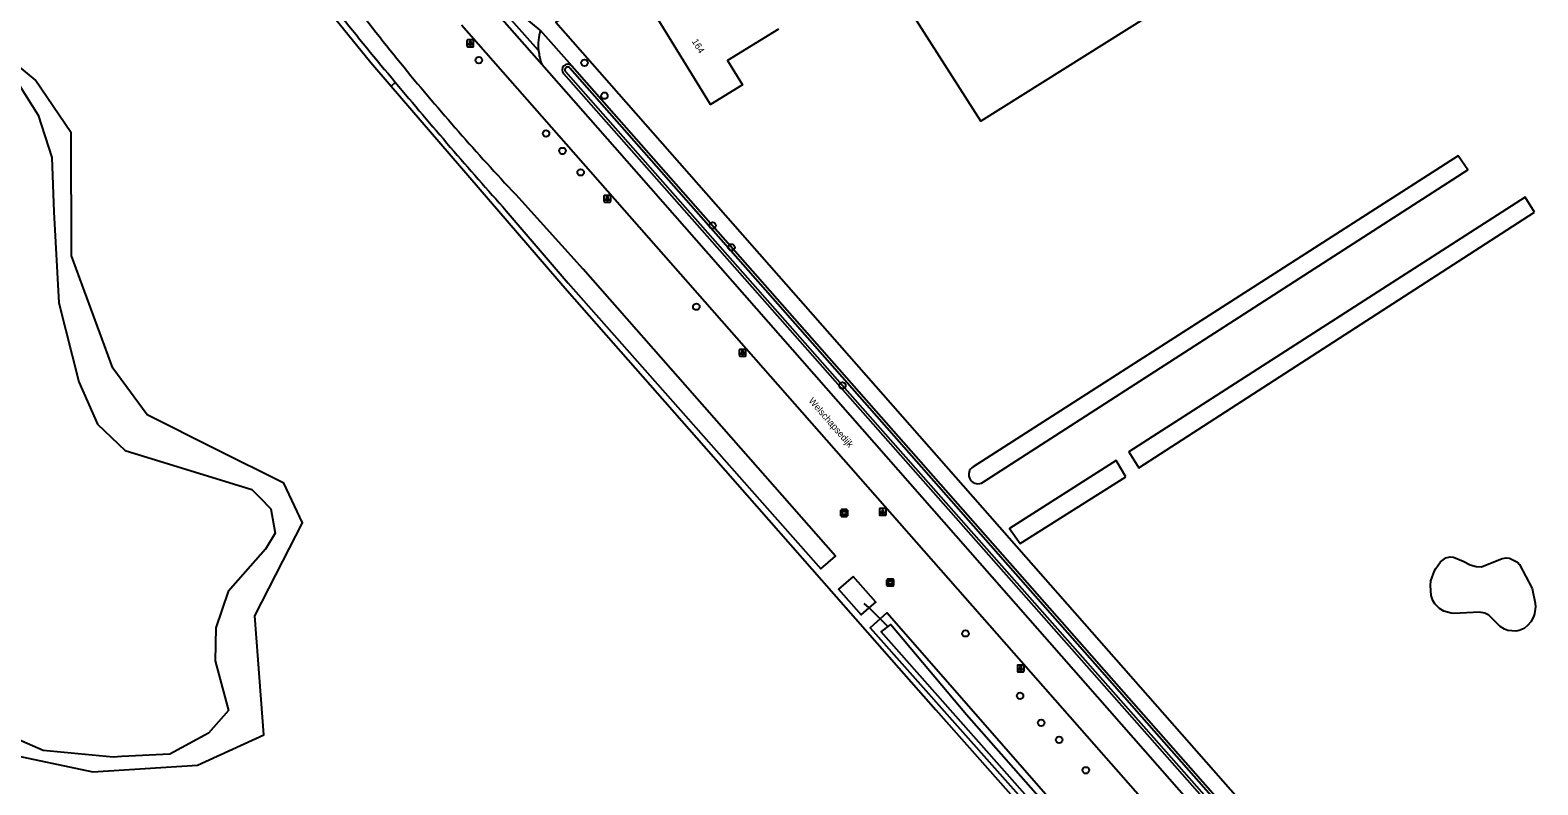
# Model space of a CAD drawing. Extents: x 156061 to 157804, y 383451 to 385640.
# Drawn here: x 157264.2 to 157488.8, y 384085.5 to 384198 of the extents above; entities that cross this region are included whole.
import ezdxf

# ---------------------------------------------------------------- set-up
doc = ezdxf.new("R2010")
doc.units = 0
for name, color, linetype in [('IMGEO_Berm_groen', 7, 'Continuous'), ('IMGEO_Boom', 7, 'Continuous'), ('IMGEO_Duiker', 7, 'Continuous'), ('IMGEO_Groenvoorziening', 7, 'Continuous'), ('IMGEO_Hek', 7, 'Continuous'), ('IMGEO_Lichtpunt', 7, 'Continuous'), ('IMGEO_Meer_plas_ven_vijver', 7, 'Continuous'), ('IMGEO_Openbare_ruimte_label', 7, 'Continuous'), ('IMGEO_Pand', 7, 'Continuous'), ('IMGEO_Pand_nummerreeks', 7, 'Continuous'), ('IMGEO_Parkeervlak_open', 7, 'Continuous'), ('IMGEO_Rijbaan_lokaal_gesloten', 7, 'Continuous'), ('IMGEO_Rijbaan_lokaal_open', 7, 'Continuous'), ('IMGEO_Verklikker', 7, 'Continuous'), ('IMGEO_Waterloop', 7, 'Continuous')]:
    doc.layers.add(name, color=color, linetype=linetype)

msp = doc.modelspace()

# ---------------------------------------------------------------- linework, layer by layer
at = {"layer": 'IMGEO_Berm_groen'}
for points in [[(157340.2, 384197.97), (157344.9, 384192.66)], [(157317.96, 384189.64), (157318.6, 384190.2)], [(157463.38, 384056.98), (157462.83, 384056.5), (157343.68, 384191.47)], [(157317.96, 384189.64), (157344.19, 384159.18), (157364.55, 384136), (157393.61, 384102.92), (157399.11, 384096.66), (157446.05, 384043.69), (157456.41, 384032.18), (157483.79, 384000), (157500, 383980.87), (157519.27, 383957.9)], [(157448.89, 384045.9), (157391.84, 384111.13), (157390.82, 384110.23), (157389.32, 384108.91), (157446.91, 384044.08), (157447.97, 384045.05)]]:
    msp.add_lwpolyline(points, dxfattribs=at)
msp.add_arc((157344.3, 384192.04), 0.853, 45.9281, 222.4567, dxfattribs=at)
at = {"layer": 'IMGEO_Boom'}
for centre in [(157331.05, 384193.51), (157346.78, 384193.11), (157349.74, 384188.2), (157341.05, 384182.56), (157343.51, 384179.96), (157346.21, 384176.77), (157365.87, 384168.86), (157368.67, 384165.6), (157363.44, 384156.75), (157385.2, 384145.03), (157403.54, 384108.07), (157411.67, 384098.76), (157414.8, 384094.75), (157417.5, 384092.21), (157421.48, 384087.66)]:
    msp.add_circle(centre, 0.489, dxfattribs=at)
at = {"layer": 'IMGEO_Duiker'}
msp.add_lwpolyline([(157391.93, 384109.15), (157390.82, 384110.23), (157389.17, 384111.85), (157388.46, 384112.54)], dxfattribs=at)
at = {"layer": 'IMGEO_Groenvoorziening'}
for points in [[(157152.75, 384380.64), (157157.1, 384375.67), (157214.42, 384310.24), (157233.65, 384288.31), (157235.49, 384286.21), (157267.06, 384250), (157294.3, 384218.6), (157310.23, 384198.96), (157314.94, 384193.15), (157317.96, 384189.64)], [(157375.38, 384222.59), (157376.59, 384220.76), (157342.51, 384199.14), (157412.58, 384119.43), (157466.22, 384058.41)], [(157260.38, 384090.24), (157273.54, 384087.41), (157289.11, 384088.41), (157299.01, 384092.93), (157298.16, 384104.12), (157297.67, 384110.68), (157301.84, 384118.84), (157304.75, 384124.52), (157301.98, 384130.44), (157291.8, 384135.54), (157281.61, 384140.64), (157276.51, 384147.57), (157270.36, 384164.31), (157270.29, 384182.67), (157264.93, 384190.55), (157259.77, 384194.82)], [(157344.9, 384192.66), (157463.98, 384057.5), (157463.38, 384056.98)], [(157477.67, 384118.84), (157478.74, 384118.28), (157479.61, 384118.03), (157480.43, 384117.98), (157483.48, 384119.23), (157484.08, 384119.32), (157484.59, 384119.3), (157485.78, 384118.66), (157486.06, 384118.35), (157487.98, 384114.75), (157488.42, 384112.58), (157488.45, 384112.03), (157488.33, 384110.99), (157488.18, 384110.55), (157487.75, 384109.78), (157487.34, 384109.28), (157486.77, 384108.81), (157486.05, 384108.5), (157485.52, 384108.4), (157484.36, 384108.49), (157483.82, 384108.7), (157483.18, 384109.1), (157481.5, 384110.76), (157480.93, 384111.09), (157480.14, 384111.22), (157476.32, 384111.02), (157475.92, 384111.06), (157474.82, 384111.39), (157474.15, 384111.79), (157473.46, 384112.48), (157473.19, 384112.96), (157472.94, 384113.69), (157472.81, 384115.22), (157472.89, 384115.91), (157473.4, 384117.41), (157473.59, 384117.76), (157474.32, 384118.74), (157475.1, 384119.31), (157475.75, 384119.5), (157476.27, 384119.45), (157477.67, 384118.84)]]:
    msp.add_lwpolyline(points, dxfattribs=at)
at = {"layer": 'IMGEO_Hek'}
msp.add_lwpolyline([(157376.59, 384220.76), (157342.51, 384199.14), (157412.58, 384119.43), (157466.22, 384058.41)], dxfattribs=at)
at = {"layer": 'IMGEO_Lichtpunt'}
for p, q in [((157329.26, 384196.41), (157329.26, 384195.6)), ((157329.26, 384196.41), (157329.26, 384195.6)), ((157330.16, 384196.5), (157329.36, 384196.5)), ((157330.16, 384196.5), (157329.36, 384196.5)), ((157329.36, 384195.5), (157330.16, 384195.5)), ((157329.36, 384195.5), (157330.16, 384195.5)), ((157330.26, 384195.6), (157330.26, 384196.41)), ((157330.26, 384195.6), (157330.26, 384196.41)), ((157349.68, 384173.24), (157349.68, 384172.43)), ((157349.68, 384173.24), (157349.68, 384172.43)), ((157350.59, 384173.33), (157349.78, 384173.33)), ((157350.59, 384173.33), (157349.78, 384173.33)), ((157349.78, 384172.34), (157350.59, 384172.34)), ((157349.78, 384172.34), (157350.59, 384172.34)), ((157350.68, 384172.43), (157350.68, 384173.24)), ((157350.68, 384172.43), (157350.68, 384173.24)), ((157369.83, 384150.3), (157369.83, 384149.49)), ((157369.83, 384150.3), (157369.83, 384149.49)), ((157370.73, 384150.39), (157369.93, 384150.39)), ((157370.73, 384150.39), (157369.93, 384150.39)), ((157370.83, 384149.49), (157370.83, 384150.3)), ((157370.83, 384149.49), (157370.83, 384150.3)), ((157369.93, 384149.4), (157370.73, 384149.4)), ((157369.93, 384149.4), (157370.73, 384149.4)), ((157390.73, 384126.57), (157390.73, 384125.76)), ((157390.73, 384126.57), (157390.73, 384125.76)), ((157391.63, 384126.66), (157390.82, 384126.66)), ((157391.63, 384126.66), (157390.82, 384126.66)), ((157390.82, 384125.66), (157391.63, 384125.66)), ((157390.82, 384125.66), (157391.63, 384125.66)), ((157391.72, 384125.76), (157391.72, 384126.57)), ((157391.72, 384125.76), (157391.72, 384126.57)), ((157411.27, 384103.25), (157411.27, 384102.45)), ((157411.27, 384103.25), (157411.27, 384102.45)), ((157412.18, 384103.35), (157411.37, 384103.35)), ((157412.18, 384103.35), (157411.37, 384103.35)), ((157412.27, 384102.45), (157412.27, 384103.25)), ((157412.27, 384102.45), (157412.27, 384103.25)), ((157411.37, 384102.35), (157412.18, 384102.35)), ((157411.37, 384102.35), (157412.18, 384102.35))]:
    msp.add_line(p, q, dxfattribs=at)
for points in [[(157329.64, 384196.07), (157329.68, 384196.04), (157329.49, 384195.78), (157329.45, 384195.81), (157329.64, 384196.07)], [(157329.74, 384196.02), (157329.79, 384196.02), (157329.79, 384195.7), (157329.74, 384195.7), (157329.74, 384196.02)], [(157329.85, 384196.04), (157329.89, 384196.07), (157330.07, 384195.81), (157330.04, 384195.78), (157329.85, 384196.04)], [(157350.06, 384172.9), (157350.1, 384172.87), (157349.91, 384172.61), (157349.87, 384172.64), (157350.06, 384172.9)], [(157350.16, 384172.85), (157350.21, 384172.85), (157350.21, 384172.53), (157350.16, 384172.53), (157350.16, 384172.85)], [(157350.27, 384172.87), (157350.31, 384172.9), (157350.49, 384172.64), (157350.46, 384172.61), (157350.27, 384172.87)], [(157370.21, 384149.96), (157370.25, 384149.93), (157370.06, 384149.67), (157370.02, 384149.7), (157370.21, 384149.96)], [(157370.31, 384149.91), (157370.36, 384149.91), (157370.36, 384149.59), (157370.31, 384149.59), (157370.31, 384149.91)], [(157370.42, 384149.93), (157370.46, 384149.96), (157370.64, 384149.7), (157370.61, 384149.67), (157370.42, 384149.93)], [(157391.1, 384126.23), (157391.14, 384126.2), (157390.95, 384125.94), (157390.91, 384125.97), (157391.1, 384126.23)], [(157391.2, 384126.18), (157391.25, 384126.18), (157391.25, 384125.86), (157391.2, 384125.86), (157391.2, 384126.18)], [(157391.31, 384126.2), (157391.35, 384126.23), (157391.54, 384125.97), (157391.5, 384125.94), (157391.31, 384126.2)], [(157411.65, 384102.92), (157411.69, 384102.89), (157411.5, 384102.63), (157411.46, 384102.66), (157411.65, 384102.92)], [(157411.75, 384102.87), (157411.8, 384102.87), (157411.8, 384102.55), (157411.75, 384102.55), (157411.75, 384102.87)], [(157411.86, 384102.89), (157411.9, 384102.92), (157412.08, 384102.65), (157412.05, 384102.63), (157411.86, 384102.89)]]:
    msp.add_lwpolyline(points, dxfattribs=at)
for centre in [(157329.76, 384196.2), (157350.18, 384173.04), (157370.33, 384150.1), (157391.23, 384126.36), (157411.77, 384103.05)]:
    msp.add_circle(centre, 0.0994, dxfattribs=at)
for centre, start, end in [((157329.36, 384196.41), 90, 180), ((157329.36, 384196.41), 90, 180), ((157329.36, 384195.6), 180, 270), ((157329.36, 384195.6), 180, 270), ((157330.16, 384196.41), 0, 90), ((157330.16, 384196.41), 0, 90), ((157330.16, 384195.6), 270, 0), ((157330.16, 384195.6), 270, 360), ((157349.78, 384173.24), 90, 180), ((157349.78, 384173.24), 90, 180), ((157349.78, 384172.43), 180, 270), ((157349.78, 384172.43), 180, 270), ((157350.59, 384173.24), 0, 90), ((157350.59, 384173.24), 0, 90), ((157350.59, 384172.43), 270, 0), ((157350.59, 384172.43), 270, 360), ((157369.93, 384150.3), 90, 180), ((157369.93, 384150.3), 90, 180), ((157370.73, 384150.3), 0, 90), ((157370.73, 384150.3), 0, 90), ((157369.93, 384149.49), 180, 270), ((157369.93, 384149.49), 180, 270), ((157370.73, 384149.49), 270, 0), ((157370.73, 384149.49), 270, 360), ((157390.82, 384126.57), 90, 180), ((157390.82, 384126.57), 90, 180), ((157390.82, 384125.76), 180, 270), ((157390.82, 384125.76), 180, 270), ((157391.63, 384126.57), 0, 90), ((157391.63, 384126.57), 0, 90), ((157391.63, 384125.76), 270, 0), ((157391.63, 384125.76), 270, 360), ((157411.37, 384103.25), 90, 180), ((157411.37, 384103.25), 90, 180), ((157411.37, 384102.45), 180, 270), ((157411.37, 384102.45), 180, 270), ((157412.18, 384103.25), 0, 90), ((157412.18, 384103.25), 0, 90), ((157412.18, 384102.45), 270, 0), ((157412.18, 384102.45), 270, 360)]:
    msp.add_arc(centre, 0.0946, start, end, dxfattribs=at)
at = {"layer": 'IMGEO_Meer_plas_ven_vijver'}
msp.add_lwpolyline([(157262.61, 384189.74), (157265.41, 384185.28), (157267.41, 384178.99), (157267.71, 384170.88), (157268.45, 384157.32), (157271.43, 384145.57), (157274.25, 384139.26), (157278.33, 384135.3), (157297.2, 384129.51), (157298.35, 384128.36), (157300.07, 384126.64), (157300.72, 384122.98), (157299.24, 384120.63), (157293.68, 384114.31), (157291.86, 384108.9), (157291.78, 384103.96), (157293.73, 384096.58), (157290.78, 384093.19), (157285.01, 384090.09), (157277.83, 384089.7), (157276.56, 384089.63), (157266.14, 384090.62), (157260.58, 384093.05)], dxfattribs=at)
at = {"layer": 'IMGEO_Pand'}
msp.add_lwpolyline([(157375.67, 384198.1), (157368.09, 384193.43), (157370.31, 384189.84), (157365.56, 384186.91), (157356.56, 384201.5)], dxfattribs=at)
at = {"layer": 'IMGEO_Parkeervlak_open'}
msp.add_lwpolyline([(157435.58, 384300.77), (157435.68, 384298.54), (157441.16, 384290.01), (157442.6, 384290.91), (157453.76, 384273.49), (157468.36, 384250), (157480.13, 384231.06), (157405.83, 384184.39), (157382.46, 384221.08)], dxfattribs=at)
at = {"layer": 'IMGEO_Rijbaan_lokaal_gesloten'}
for points in [[(157340.41, 384192.86), (157332.28, 384202.11)], [(157328.46, 384198.78), (157342.96, 384182.28), (157456.76, 384052.82)], [(157461.84, 384054.56), (157351.29, 384180.48), (157340.41, 384192.86)]]:
    msp.add_lwpolyline(points, dxfattribs=at)
at = {"layer": 'IMGEO_Rijbaan_lokaal_open'}
for points in [[(157339.93, 384194.95), (157333.81, 384201.8)], [(157340.2, 384197.97), (157334.99, 384202.22)]]:
    msp.add_lwpolyline(points, dxfattribs=at)
for centre, radius, start, end in [((157348.05, 384195.74), 8.16, 164.1263, 185.543), ((157348.05, 384195.72), 8.15, 185.4292, 200.5441)]:
    msp.add_arc(centre, radius, start, end, dxfattribs=at)
at = {"layer": 'IMGEO_Verklikker'}
for p, q in [((157384.97, 384125.61), (157384.97, 384126.41)), ((157384.97, 384126.41), (157384.97, 384125.61)), ((157385.07, 384126.51), (157385.86, 384126.51)), ((157385.86, 384126.51), (157385.07, 384126.51)), ((157385.86, 384125.51), (157385.07, 384125.51)), ((157385.07, 384125.51), (157385.86, 384125.51)), ((157385.96, 384126.41), (157385.96, 384125.61)), ((157385.96, 384125.61), (157385.96, 384126.41)), ((157391.84, 384115.24), (157391.84, 384116.04)), ((157391.84, 384116.04), (157391.84, 384115.24)), ((157391.94, 384116.14), (157392.73, 384116.14)), ((157392.73, 384116.14), (157391.94, 384116.14)), ((157392.83, 384116.04), (157392.83, 384115.24)), ((157392.83, 384115.24), (157392.83, 384116.04)), ((157392.73, 384115.14), (157391.94, 384115.14)), ((157391.94, 384115.14), (157392.73, 384115.14))]:
    msp.add_line(p, q, dxfattribs=at)
for points in [[(157385.07, 384126.25), (157385.86, 384126.25), (157385.86, 384125.78), (157385.07, 384125.78), (157385.07, 384126.25)], [(157385.14, 384126.18), (157385.14, 384125.85), (157385.79, 384125.85), (157385.79, 384126.18), (157385.14, 384126.18)], [(157391.94, 384115.87), (157392.73, 384115.87), (157392.73, 384115.41), (157391.94, 384115.41), (157391.94, 384115.87)], [(157392, 384115.81), (157392, 384115.47), (157392.66, 384115.47), (157392.66, 384115.81), (157392, 384115.81)]]:
    msp.add_lwpolyline(points, dxfattribs=at)
for centre, start, end in [((157385.07, 384126.41), 90, 180), ((157385.07, 384126.41), 90, 180), ((157385.07, 384125.61), 180, 270), ((157385.07, 384125.61), 180, 270), ((157385.86, 384126.41), 0, 90), ((157385.86, 384126.41), 360, 90), ((157385.86, 384125.61), 270, 0), ((157385.86, 384125.61), 270, 0), ((157391.94, 384116.04), 90, 180), ((157391.94, 384116.04), 90, 180), ((157392.73, 384116.04), 0, 90), ((157392.73, 384116.04), 360, 90), ((157391.94, 384115.24), 180, 270), ((157391.94, 384115.24), 180, 270), ((157392.73, 384115.24), 270, 0), ((157392.73, 384115.24), 270, 0)]:
    msp.add_arc(centre, 0.1, start, end, dxfattribs=at)
at = {"layer": 'IMGEO_Waterloop'}
for points in [[(157344.59, 384192.37), (157463.38, 384057.54), (157463.1, 384057.3), (157462.87, 384057.1), (157385.2, 384145.03), (157343.99, 384191.76)], [(157405.91, 384130.45), (157478.36, 384177.16), (157476.96, 384179.24), (157404.68, 384132.9)], [(157335.13, 384171.03), (157344.33, 384160.24), (157381.99, 384117.67), (157384.17, 384119.56), (157346.6, 384162.34), (157337.04, 384172.94)], [(157488.31, 384170.82), (157486.9, 384173.09), (157427.87, 384135.13), (157429.36, 384132.73), (157488.31, 384170.82)], [(157427.42, 384131.42), (157426.01, 384133.81), (157410.1, 384123.68), (157411.67, 384121.44), (157427.42, 384131.42)], [(157386.81, 384116.55), (157384.64, 384114.67), (157388.02, 384110.85), (157389.17, 384111.85), (157390.17, 384112.72), (157386.81, 384116.55)], [(157446.42, 384045.66), (157404.4, 384093.13), (157390.98, 384108.29), (157392.43, 384109.4), (157403.68, 384095.98), (157443.49, 384050.82), (157447.27, 384046.27), (157446.42, 384045.66)]]:
    msp.add_lwpolyline(points, dxfattribs=at)
for centre, radius, start, end in [((157602.88, 384423.61), 365.4, 217.2792, 219.3769), ((157900.4, 384675.33), 757.53, 218.81105, 219.82262), ((157344.29, 384192.06), 0.429, 45.2195, 225.3478), ((157895.42, 384671.13), 751.01, 219.81993, 221.75138), ((157599.37, 384420.91), 360.98, 219.399, 223.387), ((157405.39, 384131.73), 1.37, 121.4925, 292.1619)]:
    msp.add_arc(centre, radius, start, end, dxfattribs=at)

# ---------------------------------------------------------------- texts
at = {"layer": 'IMGEO_Openbare_ruimte_label'}
msp.add_text('Welschapsedijk', height=1, rotation=311.0674, dxfattribs=at).set_placement((157380.09, 384142.68))
at = {"layer": 'IMGEO_Pand_nummerreeks'}
msp.add_text('164', height=1, rotation=301.6557, dxfattribs=at).set_placement((157362.73, 384196.3))

doc.saveas('drawing.dxf')
